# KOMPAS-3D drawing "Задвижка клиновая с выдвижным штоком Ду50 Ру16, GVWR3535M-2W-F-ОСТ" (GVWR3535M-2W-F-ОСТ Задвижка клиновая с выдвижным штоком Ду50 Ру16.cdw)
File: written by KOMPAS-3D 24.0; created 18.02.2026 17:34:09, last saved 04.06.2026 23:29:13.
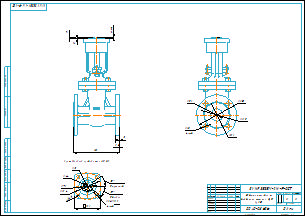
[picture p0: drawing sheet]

Document properties: Автор: R2D2; Форматы листов документа: A2; Полное имя файла: GVWR3535M-2W-F-ОСТ Задвижка клиновая с выдвижным штоком Ду50 Ру16.m3d; Масса: 12; Наименование: Задвижка клиновая с выдвижным штоком Ду50 Ру16; Количество листов документа: 1; Примечание: D040-08606

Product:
- Part/product: Задвижка клиновая с выдвижным штоком Ду50 Ру16  | designation GVWR3535M-2W-F-ОСТ
    Масса: 12
    Раздел спецификации: Прочие изделия
    Примечание: D040-08606

Views: Проекционный вид 3
Referenced files in E:\Работа\Зайцев\Для компаса\: чертеж DN.ru А3.cdt
Referenced files in E:\Работа\Зайцев\GVWR3535M-2W-F-ОСТ Задвижка клиновая 30нж941нж DN.ru Ду50-200 Ру16\исходные данные\DN50\DN50\: GVWR3535M-2W-F-ОСТ Задвижка клиновая с выдвижным штоком Ду50 Ру16.m3d
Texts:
  Присоединение привода тип АК (А)
  чертеж DN.ru А3.cdt
  Задвижка клиновая с
  выдвижным штоком Ду50
  Ру16
  GVWR3535M-2W-F-ОСТ
  Задвижка клиновая с выдвижным штоком Ду50 Ру16
  GVWR3535M-2W-F-ОСТ Задвижка клиновая с выдвижным штоком Ду50 Ру16
Dimensions and other numbers on the sheet: 100; 5 кулачков; 5 впадин; 14 (М12); 4 отв.; 13,5; 104; 70; 44; 32; 1:2; 0; 1; 2; 12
